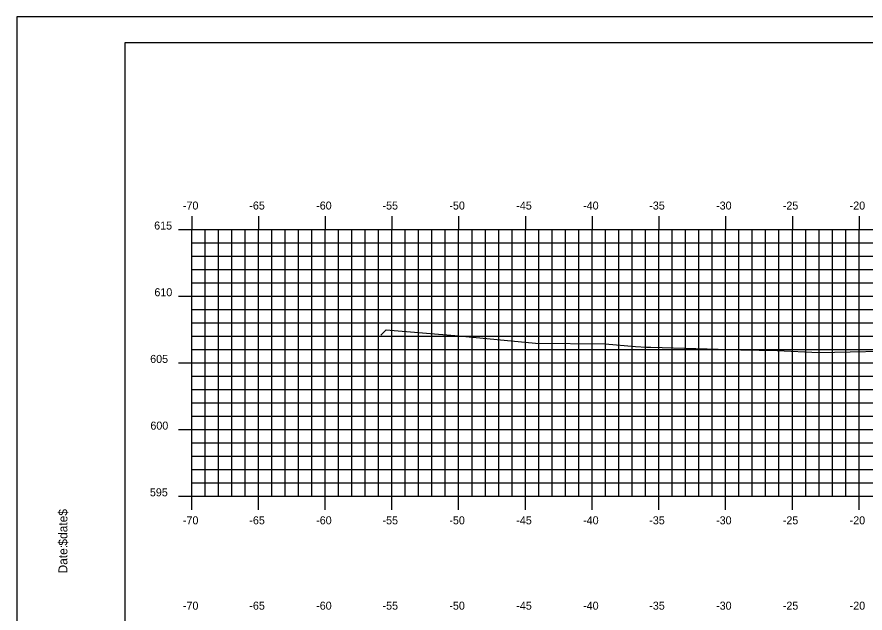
# Model space of a CAD drawing. Extents: x 1048362 to 1048532, y 780904 to 781014.
# Drawn here: x 1048362.4 to 1048425.9, y 780969.4 to 781014.1 of the extents above; entities that cross this region are included whole.
import ezdxf

# ---------------------------------------------------------------- set-up
doc = ezdxf.new("R2010")
doc.units = 0
for name, color, linetype in [('Default', 7, 'Continuous'), ('H_V ANNOTATION', 7, 'Continuous'), ('MAJOR', 7, 'Continuous'), ('MINOR', 7, 'Continuous'), ('S_Roadway_Centerline', 7, 'Continuous')]:
    doc.layers.add(name, color=color, linetype=linetype)

msp = doc.modelspace()

# ---------------------------------------------------------------- linework, layer by layer
at = {"layer": 'Default'}
for p, q in [((1048530.47, 781012.114), (1048370.47, 781012.114)), ((1048370.47, 781012.114), (1048370.47, 780907.114))]:
    msp.add_line(p, q, dxfattribs=at)
msp.add_lwpolyline([(1048362.376, 780904.055), (1048532.376, 780904.055), (1048532.376, 781014.055), (1048362.376, 781014.055)], close=True, dxfattribs=at)
at = {"layer": 'MAJOR'}
for p, q in [((1048375.469, 780999.116), (1048375.469, 780998.114)), ((1048380.469, 780999.116), (1048380.469, 780998.114)), ((1048385.469, 780999.116), (1048385.469, 780998.114)), ((1048390.469, 780999.116), (1048390.469, 780998.114)), ((1048395.469, 780999.116), (1048395.469, 780998.114)), ((1048400.469, 780999.116), (1048400.469, 780998.114)), ((1048405.469, 780999.116), (1048405.469, 780998.114)), ((1048410.469, 780999.116), (1048410.469, 780998.114)), ((1048415.469, 780999.116), (1048415.469, 780998.114)), ((1048420.469, 780999.116), (1048420.469, 780998.114)), ((1048425.469, 780999.116), (1048425.469, 780998.114)), ((1048374.467, 780998.114), (1048375.469, 780998.114)), ((1048375.469, 780998.114), (1048515.469, 780998.114)), ((1048375.469, 780978.114), (1048375.469, 780998.114)), ((1048375.469, 780978.114), (1048375.469, 780998.114)), ((1048375.469, 780998.114), (1048515.469, 780998.114)), ((1048380.469, 780978.114), (1048380.469, 780998.114)), ((1048385.469, 780978.114), (1048385.469, 780998.114)), ((1048390.469, 780978.114), (1048390.469, 780998.114)), ((1048395.469, 780978.114), (1048395.469, 780998.114)), ((1048400.469, 780978.114), (1048400.469, 780998.114)), ((1048405.469, 780978.114), (1048405.469, 780998.114)), ((1048410.469, 780978.114), (1048410.469, 780998.114)), ((1048415.469, 780978.114), (1048415.469, 780998.114)), ((1048420.469, 780978.114), (1048420.469, 780998.114)), ((1048425.469, 780978.114), (1048425.469, 780998.114)), ((1048374.467, 780993.114), (1048375.469, 780993.114)), ((1048375.469, 780993.114), (1048515.469, 780993.114)), ((1048374.467, 780988.114), (1048375.469, 780988.114)), ((1048375.469, 780988.114), (1048515.469, 780988.114)), ((1048374.467, 780983.114), (1048375.469, 780983.114)), ((1048375.469, 780983.114), (1048515.469, 780983.114)), ((1048374.467, 780978.114), (1048375.469, 780978.114)), ((1048375.469, 780978.114), (1048515.469, 780978.114)), ((1048375.469, 780978.114), (1048515.469, 780978.114)), ((1048375.469, 780977.112), (1048375.469, 780978.114)), ((1048380.469, 780977.112), (1048380.469, 780978.114)), ((1048385.469, 780977.112), (1048385.469, 780978.114)), ((1048390.469, 780977.112), (1048390.469, 780978.114)), ((1048395.469, 780977.112), (1048395.469, 780978.114)), ((1048400.469, 780977.112), (1048400.469, 780978.114)), ((1048405.469, 780977.112), (1048405.469, 780978.114)), ((1048410.469, 780977.112), (1048410.469, 780978.114)), ((1048415.469, 780977.112), (1048415.469, 780978.114)), ((1048420.469, 780977.112), (1048420.469, 780978.114)), ((1048425.469, 780977.112), (1048425.469, 780978.114))]:
    msp.add_line(p, q, dxfattribs=at)
at = {"layer": 'MINOR'}
for p, q in [((1048376.469, 780978.114), (1048376.469, 780998.114)), ((1048377.469, 780978.114), (1048377.469, 780998.114)), ((1048378.469, 780978.114), (1048378.469, 780998.114)), ((1048379.469, 780978.114), (1048379.469, 780998.114)), ((1048381.469, 780978.114), (1048381.469, 780998.114)), ((1048382.469, 780978.114), (1048382.469, 780998.114)), ((1048383.469, 780978.114), (1048383.469, 780998.114)), ((1048384.469, 780978.114), (1048384.469, 780998.114)), ((1048386.469, 780978.114), (1048386.469, 780998.114)), ((1048387.469, 780978.114), (1048387.469, 780998.114)), ((1048388.469, 780978.114), (1048388.469, 780998.114)), ((1048389.469, 780978.114), (1048389.469, 780998.114)), ((1048391.469, 780978.114), (1048391.469, 780998.114)), ((1048392.469, 780978.114), (1048392.469, 780998.114)), ((1048393.469, 780978.114), (1048393.469, 780998.114)), ((1048394.469, 780978.114), (1048394.469, 780998.114)), ((1048396.469, 780978.114), (1048396.469, 780998.114)), ((1048397.469, 780978.114), (1048397.469, 780998.114)), ((1048398.469, 780978.114), (1048398.469, 780998.114)), ((1048399.469, 780978.114), (1048399.469, 780998.114)), ((1048401.469, 780978.114), (1048401.469, 780998.114)), ((1048402.469, 780978.114), (1048402.469, 780998.114)), ((1048403.469, 780978.114), (1048403.469, 780998.114)), ((1048404.469, 780978.114), (1048404.469, 780998.114)), ((1048406.469, 780978.114), (1048406.469, 780998.114)), ((1048407.469, 780978.114), (1048407.469, 780998.114)), ((1048408.469, 780978.114), (1048408.469, 780998.114)), ((1048409.469, 780978.114), (1048409.469, 780998.114)), ((1048411.469, 780978.114), (1048411.469, 780998.114)), ((1048412.469, 780978.114), (1048412.469, 780998.114)), ((1048413.469, 780978.114), (1048413.469, 780998.114)), ((1048414.469, 780978.114), (1048414.469, 780998.114)), ((1048416.469, 780978.114), (1048416.469, 780998.114)), ((1048417.469, 780978.114), (1048417.469, 780998.114)), ((1048418.469, 780978.114), (1048418.469, 780998.114)), ((1048419.469, 780978.114), (1048419.469, 780998.114)), ((1048421.469, 780978.114), (1048421.469, 780998.114)), ((1048422.469, 780978.114), (1048422.469, 780998.114)), ((1048423.469, 780978.114), (1048423.469, 780998.114)), ((1048424.469, 780978.114), (1048424.469, 780998.114)), ((1048375.469, 780997.114), (1048515.469, 780997.114)), ((1048375.469, 780997.114), (1048376.471, 780997.114)), ((1048375.469, 780996.114), (1048515.469, 780996.114)), ((1048375.469, 780996.114), (1048376.471, 780996.114)), ((1048375.469, 780995.114), (1048515.469, 780995.114)), ((1048375.469, 780995.114), (1048376.471, 780995.114)), ((1048375.469, 780994.114), (1048515.469, 780994.114)), ((1048375.469, 780994.114), (1048376.471, 780994.114)), ((1048375.469, 780992.114), (1048515.469, 780992.114)), ((1048375.469, 780992.114), (1048376.471, 780992.114)), ((1048375.469, 780991.114), (1048515.469, 780991.114)), ((1048375.469, 780991.114), (1048376.471, 780991.114)), ((1048375.469, 780990.114), (1048515.469, 780990.114)), ((1048375.469, 780990.114), (1048376.471, 780990.114)), ((1048375.469, 780989.114), (1048515.469, 780989.114)), ((1048375.469, 780989.114), (1048376.471, 780989.114)), ((1048375.469, 780987.114), (1048515.469, 780987.114)), ((1048375.469, 780987.114), (1048376.471, 780987.114)), ((1048375.469, 780986.114), (1048515.469, 780986.114)), ((1048375.469, 780986.114), (1048376.471, 780986.114)), ((1048375.469, 780985.114), (1048515.469, 780985.114)), ((1048375.469, 780985.114), (1048376.471, 780985.114)), ((1048375.469, 780984.114), (1048515.469, 780984.114)), ((1048375.469, 780984.114), (1048376.471, 780984.114)), ((1048375.469, 780982.114), (1048515.469, 780982.114)), ((1048375.469, 780982.114), (1048376.471, 780982.114)), ((1048375.469, 780981.114), (1048515.469, 780981.114)), ((1048375.469, 780981.114), (1048376.471, 780981.114)), ((1048375.469, 780980.114), (1048515.469, 780980.114)), ((1048375.469, 780980.114), (1048376.471, 780980.114)), ((1048375.469, 780979.114), (1048515.469, 780979.114)), ((1048375.469, 780979.114), (1048376.471, 780979.114))]:
    msp.add_line(p, q, dxfattribs=at)
at = {"layer": 'S_Roadway_Centerline'}
msp.add_lwpolyline([(1048389.629, 780990.203), (1048390.04, 780990.585), (1048395.484, 780990.148), (1048401.234, 780989.595), (1048406.457, 780989.535), (1048408.712, 780989.343), (1048409.546, 780989.301), (1048409.878, 780989.291), (1048416.606, 780989.085), (1048419.322, 780989.053), (1048422.46, 780988.888), (1048429.469, 780989.042)], dxfattribs=at)

# ---------------------------------------------------------------- texts
at = {"layer": 'Default'}
for s, p in [('$date$', (1048366.155, 780974.419)), ('Date:', (1048366.155, 780972.331))]:
    msp.add_text(s, height=0.6696, rotation=90, dxfattribs=at).set_placement(p)
at = {"layer": 'H_V ANNOTATION'}
for s, p in [('-70', (1048374.811, 780999.614)), ('-65', (1048379.787, 780999.614)), ('-60', (1048384.795, 780999.614)), ('-55', (1048389.766, 780999.614)), ('-50', (1048394.774, 780999.614)), ('-45', (1048399.787, 780999.614)), ('-40', (1048404.795, 780999.614)), ('-35', (1048409.75, 780999.614)), ('-30', (1048414.758, 780999.614)), ('-25', (1048419.755, 780999.614)), ('-20', (1048424.763, 780999.614)), ('615', (1048372.658, 780998.114)), ('610', (1048372.674, 780993.114)), ('605', (1048372.358, 780988.114)), ('600', (1048372.374, 780983.114)), ('595', (1048372.337, 780978.114)), ('-70', (1048374.811, 780976.014)), ('-65', (1048379.787, 780976.014)), ('-60', (1048384.795, 780976.014)), ('-55', (1048389.766, 780976.014)), ('-50', (1048394.774, 780976.014)), ('-45', (1048399.787, 780976.014)), ('-40', (1048404.795, 780976.014)), ('-35', (1048409.75, 780976.014)), ('-30', (1048414.758, 780976.014)), ('-25', (1048419.755, 780976.014)), ('-20', (1048424.763, 780976.014)), ('-70', (1048374.811, 780969.614)), ('-65', (1048379.787, 780969.614)), ('-60', (1048384.795, 780969.614)), ('-55', (1048389.766, 780969.614)), ('-50', (1048394.774, 780969.614)), ('-45', (1048399.787, 780969.614)), ('-40', (1048404.795, 780969.614)), ('-35', (1048409.75, 780969.614)), ('-30', (1048414.758, 780969.614)), ('-25', (1048419.755, 780969.614)), ('-20', (1048424.763, 780969.614))]:
    msp.add_text(s, height=0.6, dxfattribs=at).set_placement(p)
at = {"layer": 'MAJOR'}
msp.add_text('-', height=0.006, dxfattribs=at).set_placement((1048375.465, 780978.114))

doc.saveas('drawing.dxf')
